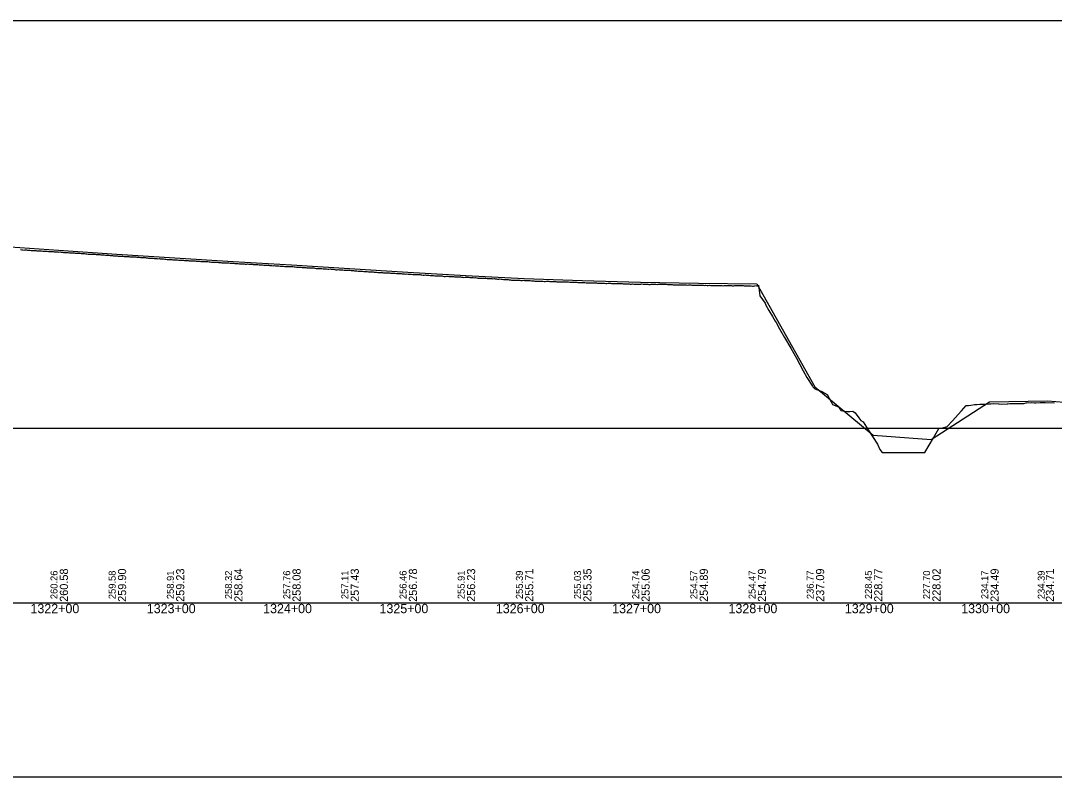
# Model space of a CAD drawing. Extents: x -3627 to 47473, y 2850 to 4350.
# Drawn here: x 19545 to 20433, y 2850 to 3500 of the extents above; entities that cross this region are included whole.
import ezdxf

# ---------------------------------------------------------------- set-up
doc = ezdxf.new("R2010")
doc.units = 0
for name, color, linetype in [('RD_DDB_Profile_EX', 7, 'Continuous'), ('RD_DDB_Profile_PR', 7, 'Continuous'), ('RD_DDB_StaTX', 7, 'Continuous'), ('RD_DDB_StripGrade', 7, 'Continuous'), ('RD_GPK_Profile_Cell', 7, 'Continuous'), ('RD_SHT_ShtClip', 7, 'Continuous')]:
    doc.layers.add(name, color=color, linetype=linetype)

msp = doc.modelspace()

# ---------------------------------------------------------------- linework, layer by layer
at = {"layer": 'RD_DDB_Profile_EX'}
for points in [[(19544.607369, 3303.308515), (19545.600928, 3303.23698), (19546.602251, 3303.07676), (19547.603296, 3302.985875), (19548.598332, 3303.03587), (19549.60476, 3303.045505), (19550.6046, 3302.864075), (19551.600844, 3302.814225), (19552.600685, 3302.744645), (19553.602006, 3302.70361), (19554.602151, 3302.613895), (19555.603194, 3302.484835), (19556.604515, 3302.45512), (19557.598074, 3302.464975)], [(19557.598074, 3302.464975), (19558.599395, 3302.40294), (19559.605524, 3302.3937), (19560.600583, 3302.293695), (19561.601904, 3302.23329), (19562.602941, 3302.16343), (19563.596501, 3302.063625), (19564.599055, 3302.00215), (19565.603935, 3301.96216), (19566.600239, 3301.86231), (19567.600045, 3301.872735), (19568.602604, 3301.791835), (19569.596162, 3301.733065), (19570.60227, 3301.69357), (19571.597347, 3301.71311), (19572.603462, 3301.57344), (19573.598533, 3301.513695), (19574.604653, 3301.38521), (19575.598214, 3301.3548), (19576.600758, 3301.31387), (19577.599406, 3301.265065), (19578.601944, 3301.30477), (19579.600597, 3301.032825), (19580.601636, 3301.07299), (19581.601789, 3300.97356), (19582.596553, 3300.88333), (19583.597876, 3300.832905), (19584.597739, 3300.79569), (19585.599062, 3300.80685), (19586.598925, 3300.677265), (19587.598775, 3300.63615), (19588.600112, 3300.606005), (19589.599968, 3300.564985), (19590.596183, 3300.52456), (19591.601161, 3300.34357), (19592.595906, 3300.31563), (19593.602354, 3300.337645), (19594.595915, 3300.143905), (19595.598415, 3300.156065), (19596.597107, 3300.088305), (19597.593283, 3299.947795), (19598.5983, 3299.888805), (19599.593028, 3299.87993), (19600.599493, 3299.748525), (19601.594216, 3299.771275), (19602.595537, 3299.525955), (19603.595404, 3299.44016), (19604.595297, 3299.489595), (19605.596591, 3299.49977), (19606.596491, 3299.32673), (19607.597779, 3299.318365), (19608.597685, 3299.31765), (19609.592395, 3299.154595), (19610.598879, 3299.18201), (19611.593584, 3299.14144), (19612.600073, 3299.091585), (19613.595035, 3298.941585), (19614.594901, 3298.851745), (19615.596222, 3298.819065), (19616.589781, 3298.778165), (19617.596279, 3298.60136), (19618.597334, 3298.56001), (19619.59229, 3298.560015), (19620.598785, 3298.510135), (19621.593478, 3298.419385), (19622.5948, 3298.36884), (19623.593539, 3298.28389), (19624.595987, 3298.07819), (19625.59094, 3298.001265), (19626.596046, 3297.951545), (19627.590994, 3297.860495), (19628.592055, 3297.769165), (19629.592181, 3297.73764), (19630.592113, 3297.669395), (19631.594565, 3297.73299), (19632.59469, 3297.692865), (19633.59462, 3297.492295), (19634.590702, 3297.46041), (19635.595813, 3297.51066), (19636.590759, 3297.45173), (19637.59182, 3297.37449), (19638.591945, 3297.10219), (19639.593269, 3297.09257), (19640.586828, 3297.14273), (19641.594455, 3297.057425), (19642.594387, 3297.006665), (19643.589337, 3297.015625), (19644.59558, 3296.90733), (19645.590523, 3296.734085), (19646.591847, 3296.724315), (19647.59171, 3296.599125), (19648.593033, 3296.51596), (19649.586592, 3296.46617), (19650.593096, 3296.45744), (19651.589159, 3296.466595), (19652.589102, 3296.28376), (19653.589224, 3296.208115), (19654.590288, 3296.125405), (19655.591611, 3296.051435), (19656.590355, 3296.06126), (19657.592798, 3295.99297)], [(19657.592798, 3295.99297), (19658.586356, 3295.86985), (19659.592863, 3295.78992), (19660.588921, 3295.593475), (19661.588866, 3295.56968), (19662.588988, 3295.508385), (19663.590052, 3295.590105), (19664.584991, 3295.411175), (19665.591239, 3295.352745), (19666.592562, 3295.38427), (19667.586121, 3295.28112), (19668.593748, 3295.11709), (19669.587307, 3295.03499), (19670.588631, 3294.877305), (19671.588494, 3294.856285), (19672.589817, 3294.793605), (19673.583376, 3294.752625), (19674.591003, 3294.78528), (19675.584562, 3294.620705), (19676.587002, 3294.602585), (19677.585749, 3294.54477), (19678.587072, 3294.49404), (19679.58174, 3294.55039), (19680.588258, 3294.33575), (19681.588209, 3294.26164), (19682.584252, 3294.23534), (19683.590768, 3294.317885), (19684.585433, 3294.168325), (19685.586764, 3293.93509), (19686.585513, 3293.89497), (19687.587946, 3293.90044), (19688.581503, 3293.900675), (19689.588023, 3293.74474), (19690.582684, 3293.69509), (19691.584015, 3293.767955), (19692.582768, 3293.68439), (19693.585196, 3293.60105), (19694.585157, 3293.591435), (19695.586377, 3293.41048), (19696.586345, 3293.35095), (19697.581265, 3293.44219), (19698.587532, 3293.369105), (19699.582446, 3293.24294), (19700.582413, 3293.200855), (19701.583627, 3293.161055), (19702.583601, 3293.04522), (19703.579612, 3293.086695), (19704.584788, 3293.060955), (19705.579697, 3293.010965), (19706.635284, 3292.916785), (19707.653283, 3292.834695), (19708.654542, 3292.586475), (19709.656223, 3292.63569), (19710.657477, 3292.6735), (19711.657699, 3292.51692), (19712.660402, 3292.443), (19713.653882, 3292.40755), (19714.655556, 3292.388665), (19715.656799, 3292.365085), (19716.65699, 3292.164385), (19717.659707, 3292.11373), (19718.653188, 3291.98207), (19719.655915, 3291.922385), (19720.656089, 3291.96258), (19721.658824, 3291.875105), (19722.658981, 3291.914985), (19723.653534, 3291.856345), (19724.655205, 3291.732945), (19725.65643, 3291.7731), (19726.658097, 3291.59072), (19727.659316, 3291.571425), (19728.652798, 3291.521675), (19729.655558, 3291.36144), (19730.660395, 3291.35252), (19731.66315, 3291.30163), (19732.663259, 3291.219665), (19733.658294, 3291.219655), (19734.659505, 3291.22863), (19735.6596, 3291.177825), (19736.662369, 3291.086675), (19737.655853, 3290.8869), (19738.663328, 3290.90649), (19739.656812, 3290.978025), (19740.659585, 3290.92727), (19741.65777, 3290.84777), (19742.659427, 3290.76812), (19743.654021, 3290.718675), (19744.660385, 3290.59981), (19745.654975, 3290.519435), (19746.661344, 3290.579125), (19747.654828, 3290.569885), (19748.657592, 3290.50004), (19749.655786, 3290.3112), (19750.658546, 3290.27932), (19751.656745, 3290.3214), (19752.658401, 3290.27029), (19753.652982, 3290.09913), (19754.65936, 3290.07105), (19755.653936, 3290.0716), (19756.660319, 3290.04994), (19757.653802, 3289.984595)], [(19757.653802, 3289.984595), (19758.655016, 3289.740295), (19759.654761, 3289.741465), (19760.655977, 3289.700325), (19761.65099, 3289.53774), (19762.655851, 3289.563385), (19763.651944, 3289.44164), (19764.656816, 3289.38276), (19765.659552, 3289.413335), (19766.653036, 3289.354275), (19767.660512, 3289.236245), (19768.653996, 3289.16439), (19769.660393, 3289.133145), (19770.654957, 3289.092905), (19771.656611, 3288.954725), (19772.651175, 3288.9146), (19773.657571, 3288.8963), (19774.651056, 3288.846585), (19775.653791, 3288.854945), (19776.653925, 3288.84467), (19777.653236, 3288.75605), (19778.654887, 3288.754835), (19779.649452, 3288.50544), (19780.650671, 3288.50483), (19781.657066, 3288.36434), (19782.651631, 3288.26491), (19783.651766, 3288.17332), (19784.654501, 3288.141205), (19785.653811, 3288.183605), (19786.653946, 3287.96996), (19787.650028, 3287.970175), (19788.650163, 3287.97297), (19789.656126, 3288.05516), (19790.652206, 3287.792535), (19791.652341, 3287.75109), (19792.64691, 3287.72371), (19793.648563, 3287.74462), (19794.65452, 3287.704775), (19795.649089, 3287.6461), (19796.649219, 3287.67651), (19797.645308, 3287.291955), (19798.650187, 3287.2109), (19799.651398, 3287.201175), (19800.646403, 3287.10117), (19801.647616, 3287.09139), (19802.646936, 3287.13377), (19803.648582, 3287.04559), (19804.649794, 3286.863605), (19805.643281, 3286.804555), (19806.650762, 3286.795815), (19807.645329, 3286.82419), (19808.643573, 3286.6757), (19809.646292, 3286.54335), (19810.644541, 3286.689895), (19811.645759, 3286.60756), (19812.646569, 3286.44561), (19813.640055, 3286.42769), (19814.646058, 3286.17357), (19815.641018, 3286.04648), (19816.645975, 3286.08787), (19817.642403, 3286.17452), (19818.642131, 3286.05307), (19819.647522, 3286.00299), (19820.64247, 3285.952995), (19821.648905, 3285.96219), (19822.64385, 3285.739025), (19823.642539, 3285.689995), (19824.644189, 3285.65686), (19825.643917, 3285.607965), (19826.644527, 3285.594155), (19827.64426, 3285.563515), (19828.639196, 3285.472405), (19829.645638, 3285.340375), (19830.639539, 3285.25458), (19831.645982, 3285.09919), (19832.640916, 3285.0992), (19833.640632, 3285.0828), (19834.64126, 3284.840275), (19835.642422, 3284.782505), (19836.644086, 3284.722515), (19837.64277, 3284.756), (19838.637695, 3284.75601), (19839.644142, 3284.66508), (19840.639065, 3284.473895), (19841.644491, 3284.47383), (19842.639414, 3284.459075), (19843.641083, 3284.331515), (19844.640784, 3284.33289), (19845.641428, 3284.33146), (19846.643093, 3284.19818), (19847.638036, 3284.107115), (19848.64447, 3284.057305), (19849.638377, 3283.98026), (19850.640048, 3283.92012), (19851.641718, 3283.80513), (19852.640384, 3283.68303), (19853.643535, 3283.577635), (19854.645212, 3283.630815), (19855.640188, 3283.58995), (19856.645539, 3283.498985), (19857.640516, 3283.476395)], [(19857.640516, 3283.476395), (19858.641754, 3283.384975), (19859.642989, 3283.36602), (19860.641202, 3283.29508), (19861.642435, 3283.37627), (19862.645168, 3283.0938), (19863.639709, 3283.044305), (19864.644618, 3283.00387), (19865.639158, 3282.986135), (19866.641889, 3282.967045), (19867.642059, 3282.925305), (19868.641342, 3282.909045), (19869.642575, 3282.776645), (19870.64424, 3282.725505), (19871.638784, 3282.676065), (19872.640016, 3282.634675), (19873.639297, 3282.60015), (19874.640966, 3282.394555), (19875.642197, 3282.34404), (19876.641483, 3282.39574), (19877.641656, 3282.235835), (19878.637687, 3282.186125), (19879.643669, 3282.145915), (19880.637151, 3282.18709), (19881.638384, 3282.054705), (19882.63915, 3281.897095), (19883.640389, 3281.88755), (19884.63387, 3281.88779), (19885.639871, 3281.88851), (19886.642577, 3281.88364), (19887.636059, 3281.83396), (19888.642064, 3281.793875), (19889.636588, 3281.6124), (19890.643023, 3281.471565), (19891.637543, 3281.38103), (19892.638782, 3281.594755), (19893.638079, 3281.408795), (19894.639738, 3281.366745), (19895.634251, 3281.2406), (19896.640695, 3281.16428), (19897.634178, 3281.08222), (19898.635419, 3281.140495), (19899.635135, 3281.00935), (19900.636378, 3280.92357), (19901.636092, 3280.848735), (19902.637336, 3280.798025), (19903.638992, 3280.879005), (19904.638295, 3280.831455), (19905.639951, 3280.7476), (19906.634456, 3280.707015), (19907.63948, 3280.64632), (19908.63541, 3280.316625), (19909.635637, 3280.374445), (19910.636364, 3280.391385), (19911.636597, 3280.390285), (19912.632522, 3280.266825), (19913.637558, 3280.09343), (19914.631042, 3280.13498), (19915.638518, 3280.116215), (19916.632003, 3280.125215), (19917.639479, 3280.069005), (19918.632963, 3279.86067), (19919.635624, 3279.859715), (19920.633924, 3279.904375), (19921.63658, 3279.895025), (19922.634884, 3279.888), (19923.636136, 3279.571635), (19924.635845, 3279.614215), (19925.630314, 3279.514655), (19926.631974, 3279.529655), (19927.63029, 3279.556025), (19928.631943, 3279.604685), (19929.632623, 3279.523475), (19930.632904, 3279.264765), (19931.632604, 3279.265915), (19932.63426, 3279.34747), (19933.633562, 3279.308165), (19934.635219, 3279.223625), (19935.630075, 3279.248455), (19936.635203, 3278.99904), (19937.630055, 3278.865815), (19938.636166, 3278.858335), (19939.631012, 3278.825025), (19940.637518, 3278.75857), (19941.631003, 3278.833875), (19942.633628, 3278.724635), (19943.633317, 3278.67616), (19944.626799, 3278.726435), (19945.633327, 3278.526665), (19946.629157, 3278.493895), (19947.634366, 3278.4526), (19948.629235, 3278.468955), (19949.630941, 3278.450715), (19950.629316, 3278.335715), (19951.631976, 3278.393385), (19952.63232, 3278.358705), (19953.632081, 3278.151435), (19954.633861, 3278.02508), (19955.628433, 3277.96699), (19956.635062, 3278.133545), (19957.630029, 3277.924925)], [(19957.630029, 3277.924925), (19958.635293, 3277.84172), (19959.631229, 3277.725035), (19960.633021, 3277.67344), (19961.63149, 3277.716505), (19962.633357, 3277.78982), (19963.628024, 3277.614525), (19964.634723, 3277.40641), (19965.62841, 3277.42232), (19966.63609, 3277.19768), (19967.629777, 3277.197415), (19968.632637, 3277.18756), (19969.631172, 3277.09706), (19970.632717, 3277.11291), (19971.627894, 3277.153695), (19972.63425, 3277.153695), (19973.629432, 3277.04253), (19974.630979, 3276.86698), (19975.637728, 3276.875145), (19976.631497, 3277.048325), (19977.639291, 3276.9243), (19978.633144, 3276.776495), (19979.634754, 3276.713035), (19980.634845, 3276.745705), (19981.636452, 3276.7028), (19982.631777, 3276.674665), (19983.638151, 3276.6244), (19984.638248, 3276.46092), (19985.63795, 3276.54394), (19986.636666, 3276.357015), (19987.630121, 3276.308125), (19988.629874, 3276.3499), (19989.630046, 3276.317705), (19990.629797, 3276.256805), (19991.634759, 3276.332495), (19992.634513, 3276.33345), (19993.634708, 3276.26823), (19994.627763, 3276.078655), (19995.626607, 3276.06178), (19996.627845, 3276.09626), (19997.626691, 3276.12089), (19998.626936, 3276.08676), (19999.631592, 3276.047695), (20000.631832, 3275.972395), (20001.631702, 3275.85665), (20002.625204, 3275.88289), (20003.625128, 3275.916525), (20004.625051, 3275.8919), (20005.624975, 3275.792295), (20006.629733, 3275.74454), (20007.628315, 3275.795245), (20008.629191, 3275.746005), (20009.62915, 3275.545185), (20010.622294, 3275.62879), (20011.621921, 3275.739), (20012.621938, 3275.60517), (20013.621955, 3275.598955), (20014.625535, 3275.68531), (20015.626476, 3275.543735), (20016.619588, 3275.49549), (20017.624525, 3275.405225), (20018.624261, 3275.29454), (20019.61744, 3275.472515), (20020.622455, 3275.508765), (20021.622564, 3275.35498), (20022.615354, 3275.322745), (20023.620385, 3275.1548), (20024.620494, 3275.07715), (20025.619446, 3275.12303), (20026.61844, 3275.12284), (20027.618643, 3275.14278), (20028.617638, 3275.139265), (20029.617844, 3275.074135), (20030.616852, 3274.860355), (20031.615, 3274.792205), (20032.616036, 3274.73463), (20033.621236, 3274.76472), (20034.61333, 3274.872975), (20035.614452, 3274.87252), (20036.619724, 3274.83838), (20037.611819, 3274.796745), (20038.612117, 3274.79585), (20039.618212, 3274.81149), (20040.611446, 3274.60411), (20041.615635, 3274.57589), (20042.616829, 3274.46994), (20043.617223, 3274.633995), (20044.612299, 3274.616915), (20045.619729, 3274.56337), (20046.614809, 3274.56113), (20047.615202, 3274.35273), (20048.617281, 3274.34851), (20049.617703, 3274.42475), (20050.619064, 3274.481095), (20051.620321, 3274.371835), (20052.621704, 3274.15148), (20053.622898, 3274.21173), (20054.624303, 3274.226525), (20055.618583, 3274.27338), (20056.626861, 3274.278775), (20057.621154, 3274.26737)], [(20057.621154, 3274.26737), (20058.622695, 3274.17421), (20059.623837, 3274.17676), (20060.6254, 3274.225215), (20061.632321, 3274.15479), (20062.628063, 3273.844395), (20063.628211, 3273.84339), (20064.630683, 3273.960785), (20065.630851, 3273.982185), (20066.626729, 3274.069605), (20067.633599, 3273.983195), (20068.629493, 3273.775755), (20069.637864, 3273.751165), (20070.636937, 3273.79965), (20071.633994, 3273.74524), (20072.639591, 3273.76257), (20073.636726, 3273.750285), (20074.635821, 3273.788535), (20075.635885, 3273.74997), (20076.633143, 3273.651305), (20077.639729, 3273.731385), (20078.638159, 3273.8135), (20079.632345, 3273.77219), (20080.637316, 3273.72249), (20081.63578, 3273.6633), (20082.635898, 3273.67394), (20083.640982, 3273.685965), (20084.633645, 3273.363775), (20085.632168, 3273.34412), (20086.632273, 3273.73817), (20087.63737, 3273.61731), (20088.635893, 3273.520535), (20089.62972, 3273.631645), (20090.63492, 3273.519975), (20091.635108, 3273.44022), (20092.632597, 3273.51233), (20093.637805, 3273.56206), (20094.631685, 3273.54231), (20095.631866, 3273.662575), (20096.637077, 3273.6219), (20097.63573, 3273.573175), (20098.629701, 3273.524495), (20099.635446, 3273.522845), (20100.634159, 3273.391205), (20101.632872, 3273.282665), (20102.631585, 3273.283705), (20103.633715, 3273.300175), (20104.632423, 3273.25114), (20105.637764, 3273.192955), (20106.631835, 3273.16283), (20107.633186, 3273.090125), (20108.636551, 3273.06954), (20109.63674, 3273.035815), (20110.631522, 3273.03732), (20111.636453, 3273.108105), (20112.637784, 3273.15778), (20113.629866, 3273.20782), (20114.636034, 3273.147055), (20115.636288, 3273.074365), (20116.631184, 3272.97352), (20117.63618, 3272.90428), (20118.635987, 3273.02331), (20119.636214, 3273.080835), (20120.635877, 3273.14272), (20121.636134, 3272.860375), (20122.636002, 3272.839105), (20123.634579, 3272.779935), (20124.636496, 3272.76743), (20125.637655, 3272.783095), (20126.635446, 3272.782785), (20127.637821, 3272.858485), (20128.63898, 3272.814645), (20129.644859, 3272.81216), (20130.639267, 3272.7708), (20131.640515, 3272.670245), (20132.646416, 3272.64637), (20133.641329, 3272.67195), (20134.642106, 3272.495945), (20135.647972, 3272.577395), (20136.649204, 3272.66822), (20137.644221, 3272.51584), (20138.651503, 3272.513885), (20139.650972, 3272.51049), (20140.646094, 3272.581315), (20141.653376, 3272.491275), (20142.65472, 3272.44987), (20143.652487, 3272.563375), (20144.653813, 3272.533945), (20145.654994, 3272.505965), (20146.656436, 3272.46653), (20147.655864, 3272.36405), (20148.655673, 3272.35022), (20149.658598, 3272.5089), (20150.658424, 3272.395385), (20151.657793, 3272.391915), (20152.66516, 3272.389795), (20153.660638, 3272.423935), (20154.666551, 3272.444685), (20155.665917, 3272.44053), (20156.663093, 3272.34746), (20157.668962, 3272.270995)], [(20157.668962, 3272.270995), (20158.664599, 3272.363135), (20159.666929, 3272.446675), (20160.665536, 3272.47397), (20161.664275, 3272.515845), (20162.663, 3272.515875), (20163.661828, 3272.55692), (20164.660578, 3272.396815), (20165.665349, 3272.410315), (20166.658212, 3272.34452), (20167.658574, 3272.210495), (20168.655897, 3272.17153), (20169.656304, 3272.195465), (20170.659656, 3272.14576), (20171.652629, 3272.318005), (20172.65759, 3272.13923), (20173.650573, 3272.06577), (20174.65556, 3272.055455), (20175.654464, 3272.181005), (20176.652744, 3272.392925), (20177.395467, 3272.353075), (20178.129114, 3272.31421), (20178.870759, 3272.878295), (20179.920809, 3263.70782), (20184.480552, 3257.216155), (20185.261088, 3255.749865), (20187.72166, 3251.126065), (20190.868688, 3245.957725), (20193.260364, 3241.87312), (20193.926183, 3240.7356), (20196.900037, 3235.215755), (20201.259639, 3227.896875), (20206.70834, 3218.74596), (20209.258914, 3214.06291), (20211.47144, 3209.99918), (20217.25819, 3199.13983), (20220.325717, 3193.381525), (20225.257465, 3185.91674), (20225.576115, 3185.43424), (20227.406338, 3183.793785), (20232.616353, 3181.73621), (20233.25674, 3181.392345), (20237.768407, 3178.967135), (20241.256016, 3172.52732), (20242.478576, 3170.269455), (20247.720744, 3168.27979), (20249.255291, 3165.68717), (20249.576615, 3165.14423), (20254.782099, 3164.159695), (20257.254567, 3164.30481), (20259.935348, 3164.46204), (20261.843482, 3163.22972), (20265.253842, 3158.781465), (20266.962036, 3156.55347), (20268.904898, 3155.249715), (20273.253117, 3148.58291), (20281.252393, 3136.17799), (20283.211766, 3131.66045), (20285.092973, 3128.95), (20289.251668, 3128.95), (20297.250943, 3128.95), (20301.140757, 3128.95), (20305.250219, 3128.95), (20307.361198, 3128.95), (20313.249494, 3128.95), (20321.248769, 3128.95), (20321.742706, 3128.95), (20329.248045, 3141.76793), (20333.788934, 3149.523635), (20337.368404, 3150.282975), (20340.900584, 3151.343615), (20345.246595, 3156.098625), (20353.245871, 3164.851925), (20357.363517, 3169.35834), (20359.330868, 3169.34646), (20361.245146, 3169.68596), (20364.425925, 3170.25068), (20366.419055, 3170.37877), (20369.244421, 3170.44076), (20371.488445, 3170.49041), (20373.506706, 3170.620795), (20377.243697, 3170.862215), (20378.55108, 3170.94692), (20380.593826, 3170.992495), (20385.242972, 3170.768205), (20385.613838, 3170.75038), (20387.680422, 3170.665685), (20392.676734, 3170.778195), (20393.242247, 3170.850985), (20394.766498, 3171.047445), (20399.739771, 3171.162035), (20401.241523, 3171.164745), (20401.852059, 3171.165955), (20406.802948, 3171.210685), (20408.937087, 3171.607655), (20409.240798, 3171.629855), (20413.866268, 3171.968695), (20416.021563, 3171.775675), (20417.240073, 3171.847145), (20420.929738, 3172.06422), (20423.105542, 3172.06901)], [(20423.105542, 3172.06901), (20425.239349, 3172.00738), (20433.238624, 3171.777745)]]:
    msp.add_lwpolyline(points, dxfattribs=at)
at = {"layer": 'RD_DDB_Profile_PR'}
msp.add_lwpolyline([(19527.33, 3306.1735), (19577.33, 3302.878), (19627.33, 3299.4845), (19677.33, 3296.1595), (19727.33, 3293.178), (19777.33, 3290.3845), (19827.33, 3287.173), (19877.33, 3283.8855), (19927.33, 3281.148), (19977.33, 3278.5625), (20027.33, 3276.737), (20077.33, 3275.3065), (20127.33, 3274.435), (20177.33, 3273.9565), (20227.33, 3185.462), (20277.33, 3143.8605), (20327.33, 3140.092), (20377.33, 3172.468), (20427.33, 3173.5475), (20477.33, 3169.518)], dxfattribs=at)
at = {"layer": 'RD_GPK_Profile_Cell'}
msp.add_line((1000, 3000), (46705.077602, 3000), dxfattribs=at)
at = {"layer": 'RD_SHT_ShtClip'}
for points in [[(18953.33, 3500), (18953.33, 3000), (20453.33, 3000), (20453.33, 3000), (20453.33, 3500), (20453.33, 3500)], [(18933.33, 3150), (20473.33, 3150), (20473.33, 2850), (18933.33, 2850)]]:
    msp.add_lwpolyline(points, close=True, dxfattribs=at)

# ---------------------------------------------------------------- texts
at = {"layer": 'RD_DDB_StaTX'}
for s, p in [('1322+00', (19553.125471, 2991)), ('1323+00', (19653.125471, 2991)), ('1324+00', (19753.125471, 2991)), ('1325+00', (19853.125471, 2991)), ('1326+00', (19953.125471, 2991)), ('1327+00', (20053.125471, 2991)), ('1328+00', (20153.125471, 2991)), ('1329+00', (20253.125471, 2991)), ('1330+00', (20353.125471, 2991))]:
    msp.add_text(s, height=8, dxfattribs=at).set_placement(p)
at = {"layer": 'RD_DDB_StripGrade'}
for s, height, p in [('260.26', 6, (19576.33, 3003.073688)), ('260.58', 7, (19585.33, 3000.75)), ('259.58', 6, (19626.33, 3003.073688)), ('259.90', 7, (19635.33, 3000.75)), ('258.91', 6, (19676.33, 3003.073688)), ('259.23', 7, (19685.33, 3000.75)), ('258.32', 6, (19726.33, 3003.073688)), ('258.64', 7, (19735.33, 3000.75)), ('257.76', 6, (19776.33, 3003.073688)), ('258.08', 7, (19785.33, 3000.75)), ('257.11', 6, (19826.33, 3003.073688)), ('257.43', 7, (19835.33, 3000.75)), ('256.46', 6, (19876.33, 3003.073688)), ('256.78', 7, (19885.33, 3000.75)), ('255.91', 6, (19926.33, 3003.073688)), ('256.23', 7, (19935.33, 3000.75)), ('255.39', 6, (19976.33, 3003.073688)), ('255.71', 7, (19985.33, 3000.75)), ('255.03', 6, (20026.33, 3003.073688)), ('255.35', 7, (20035.33, 3000.75)), ('254.74', 6, (20076.33, 3003.073688)), ('255.06', 7, (20085.33, 3000.75)), ('254.57', 6, (20126.33, 3003.073688)), ('254.89', 7, (20135.33, 3000.75)), ('254.47', 6, (20176.33, 3003.073688)), ('254.79', 7, (20185.33, 3000.75)), ('236.77', 6, (20226.33, 3003.073688)), ('237.09', 7, (20235.33, 3000.75)), ('228.45', 6, (20276.33, 3003.073688)), ('228.77', 7, (20285.33, 3000.75)), ('227.70', 6, (20326.33, 3003.073688)), ('228.02', 7, (20335.33, 3000.75)), ('234.17', 6, (20376.33, 3003.073688)), ('234.49', 7, (20385.33, 3000.75)), ('234.39', 6, (20424.918025, 3003.073688)), ('234.71', 7, (20432.867854, 3000.75))]:
    msp.add_text(s, height=height, rotation=90, dxfattribs=at).set_placement(p)

doc.saveas('drawing.dxf')
